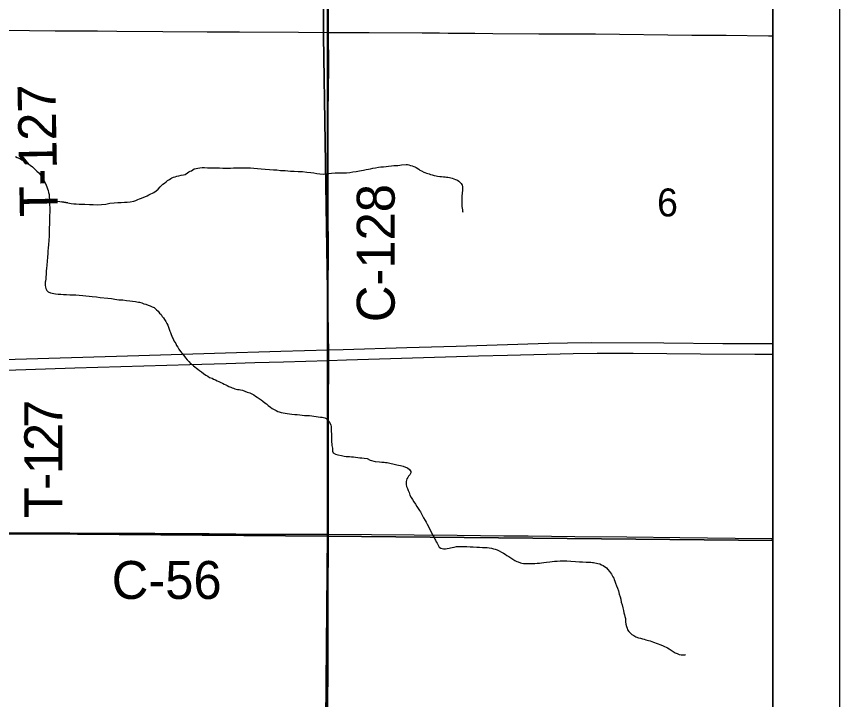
# Model space of a CAD drawing. Extents: x -17 to 88, y -5 to 22.
# Drawn here: x 8.268 to 9.5, y 18.897 to 19.92 of the extents above; entities that cross this region are included whole.
import ezdxf

# ---------------------------------------------------------------- set-up
doc = ezdxf.new("R2010")
doc.units = 0
for name, color, linetype in [('GM_X_County_Road', 7, 'Continuous'), ('GM_X_County_Road_Text', 7, 'Continuous'), ('GM_X_Minor_River', 7, 'Continuous'), ('GM_X_Section', 7, 'Continuous'), ('GM_X_Section_Text', 7, 'Continuous'), ('GM_X_Township', 7, 'Continuous'), ('GM_X_Township_Road', 7, 'Continuous'), ('GM_X_Township_Road_Text', 7, 'Continuous'), ('GM_X_US_Route', 7, 'Continuous'), ('SH_Data', 7, 'Continuous')]:
    doc.layers.add(name, color=color, linetype=linetype)

msp = doc.modelspace()

# ---------------------------------------------------------------- linework, layer by layer
at = {"layer": 'GM_X_County_Road'}
for points in [[(8.7347, 19.8958), (8.7347, 19.9018), (8.7346, 19.9229), (8.7345, 19.9503), (8.7345, 19.9913), (8.7345, 20.0248), (8.7345, 20.0534), (8.7345, 20.0913), (8.7345, 20.1174), (8.7345, 20.1646)], [(8.7345, 19.4204), (8.7345, 19.43), (8.7345, 19.4561), (8.7345, 19.5168), (8.7347, 19.5616), (8.7349, 19.5813), (8.7344, 19.6151), (8.7344, 19.6362), (8.7345, 19.6617), (8.7344, 19.6816), (8.7345, 19.7307), (8.7345, 19.7611), (8.7345, 19.7847), (8.7348, 19.8004), (8.735, 19.8164), (8.7352, 19.8367), (8.7352, 19.8565), (8.7348, 19.8832), (8.7347, 19.8958)], [(8.7345, 19.4044), (8.7345, 19.4133), (8.7345, 19.4204)], [(8.7348, 19.1441), (8.7347, 19.1665), (8.735, 19.1901), (8.7347, 19.2274), (8.7346, 19.2802), (8.7345, 19.3169), (8.7345, 19.3983), (8.7345, 19.4044)], [(8.237, 19.1467), (8.3475, 19.1462), (8.4749, 19.1455), (8.5563, 19.145), (8.5961, 19.1448), (8.6526, 19.1443), (8.7005, 19.1443), (8.7348, 19.1441)], [(8.733, 18.1413), (8.7329, 18.1995), (8.7329, 18.2468), (8.733, 18.2834), (8.7331, 18.3338), (8.7331, 18.3692), (8.7333, 18.4114), (8.7335, 18.4661), (8.7337, 18.5134), (8.7337, 18.583), (8.7338, 18.6588), (8.734, 18.765), (8.734, 18.8744), (8.7343, 18.9558), (8.7343, 19.0435), (8.7348, 19.1441)], [(8.7348, 19.1441), (8.9273, 19.1427), (8.9975, 19.1419), (9.0336, 19.1416), (9.1038, 19.1407), (9.1814, 19.1401), (9.261, 19.1394), (9.3436, 19.1383), (9.3977, 19.1378), (9.4, 19.1378)]]:
    msp.add_lwpolyline(points, dxfattribs=at)
at = {"layer": 'GM_X_Minor_River'}
for points in [[(8.266, 19.7098), (8.2687, 19.7083), (8.2728, 19.7067), (8.2754, 19.7051), (8.2784, 19.7032), (8.2815, 19.7012), (8.2848, 19.6992), (8.2882, 19.6969), (8.2916, 19.6942), (8.295, 19.6911), (8.2979, 19.688), (8.3009, 19.6856), (8.3032, 19.6829), (8.305, 19.6795), (8.3072, 19.6768), (8.3083, 19.6745), (8.312, 19.6668), (8.3131, 19.6642), (8.3142, 19.6615), (8.3149, 19.6588), (8.3156, 19.6558), (8.3163, 19.6527), (8.3166, 19.65), (8.3169, 19.6451), (8.3172, 19.6413), (8.3171, 19.6375), (8.3174, 19.6333), (8.3174, 19.6291), (8.3173, 19.6257), (8.3172, 19.6227), (8.3172, 19.6181), (8.3171, 19.6132), (8.317, 19.6083), (8.3165, 19.603), (8.3164, 19.5969), (8.3163, 19.5912), (8.3158, 19.584), (8.3153, 19.5779), (8.3148, 19.5726), (8.3143, 19.5688), (8.3143, 19.5646), (8.3141, 19.5589), (8.3137, 19.5529), (8.3132, 19.5472), (8.3127, 19.5423), (8.3122, 19.5385), (8.3118, 19.5347), (8.3118, 19.5328), (8.3113, 19.5301), (8.3113, 19.5267), (8.3108, 19.5233), (8.3104, 19.5214), (8.3107, 19.5172), (8.311, 19.5142), (8.3114, 19.5123), (8.3128, 19.5092), (8.3151, 19.5073), (8.3185, 19.5057), (8.326, 19.504), (8.3302, 19.5036), (8.334, 19.5035), (8.3378, 19.5034), (8.3424, 19.503), (8.3473, 19.5029), (8.3519, 19.5028), (8.3564, 19.5027), (8.3614, 19.5023), (8.3667, 19.5018), (8.3716, 19.5013), (8.3766, 19.5008), (8.3811, 19.5004), (8.3876, 19.4995), (8.3929, 19.4986), (8.4042, 19.4977), (8.4096, 19.4972), (8.4149, 19.4963), (8.4209, 19.4954), (8.4266, 19.495), (8.4323, 19.4941), (8.4373, 19.4936), (8.4414, 19.4932), (8.4456, 19.4927), (8.4479, 19.4923), (8.4501, 19.4919), (8.452, 19.4915), (8.4554, 19.4906), (8.4585, 19.4894), (8.4611, 19.4886), (8.4645, 19.4874), (8.4679, 19.4862), (8.4709, 19.4846), (8.4736, 19.4835), (8.4754, 19.4823), (8.4773, 19.4804), (8.4795, 19.478), (8.4818, 19.4753), (8.484, 19.473), (8.4859, 19.4703), (8.4877, 19.468), (8.4892, 19.4657), (8.4914, 19.4626)], [(8.7564, 19.6852), (8.7617, 19.6854), (8.7667, 19.6861), (8.7713, 19.6868), (8.7762, 19.6874), (8.7812, 19.6885), (8.7873, 19.6895), (8.7911, 19.6902), (8.7945, 19.6909), (8.7976, 19.6916), (8.8014, 19.6923), (8.8052, 19.693), (8.8094, 19.6937), (8.8132, 19.6944), (8.817, 19.6943), (8.8212, 19.695), (8.8247, 19.6953), (8.8292, 19.696), (8.8327, 19.6963), (8.8357, 19.6966), (8.8384, 19.6965), (8.8414, 19.6969), (8.8441, 19.6972), (8.8513, 19.6978), (8.8532, 19.6978), (8.8551, 19.6974), (8.8574, 19.6966), (8.86, 19.6961), (8.8623, 19.695), (8.8642, 19.6942), (8.8661, 19.6934), (8.8698, 19.691), (8.8717, 19.6895), (8.8739, 19.6883), (8.8773, 19.6863), (8.8792, 19.6859), (8.8815, 19.6851), (8.8853, 19.6839), (8.8875, 19.6831), (8.8902, 19.6823), (8.8932, 19.6815), (8.8959, 19.681), (8.8981, 19.6806), (8.9015, 19.6798), (8.9038, 19.6798), (8.9069, 19.6793), (8.9095, 19.6793), (8.9114, 19.6789), (8.9137, 19.6788), (8.916, 19.6784), (8.9179, 19.678), (8.9198, 19.6776), (8.9224, 19.6764), (8.925, 19.6756), (8.9277, 19.6744), (8.9299, 19.6728), (8.9333, 19.6693), (8.9348, 19.667), (8.9355, 19.6647), (8.9354, 19.6628), (8.9354, 19.6594), (8.9345, 19.6503), (8.9344, 19.6469), (8.9343, 19.6431), (8.9343, 19.6401), (8.9346, 19.6378), (8.9345, 19.6351), (8.9349, 19.6325), (8.9352, 19.6298), (8.9355, 19.6275), (8.9363, 19.6264), (8.9359, 19.6264)], [(8.3169, 19.6451), (8.3446, 19.6404), (8.3355, 19.6421), (8.3446, 19.6404), (8.3495, 19.6396), (8.3533, 19.6391), (8.3571, 19.639), (8.3613, 19.6386), (8.3654, 19.6385), (8.37, 19.6384), (8.3768, 19.6379), (8.3825, 19.6378), (8.3886, 19.6377), (8.3951, 19.638), (8.4012, 19.6386), (8.4073, 19.64), (8.4138, 19.6406), (8.4195, 19.6409), (8.4244, 19.6412), (8.4294, 19.6415), (8.4332, 19.6414), (8.4378, 19.6421), (8.4431, 19.6431), (8.4462, 19.6442), (8.4492, 19.6453), (8.4519, 19.6464), (8.4546, 19.6475), (8.4634, 19.6511), (8.4657, 19.6522), (8.4688, 19.6537), (8.4711, 19.6548), (8.4734, 19.6559), (8.4765, 19.6585), (8.4795, 19.6611), (8.4827, 19.6644), (8.485, 19.6667), (8.4869, 19.6685), (8.4892, 19.67), (8.4915, 19.6719), (8.4939, 19.6741), (8.4965, 19.6756), (8.4985, 19.6767), (8.5004, 19.6778), (8.5027, 19.6789), (8.505, 19.6796), (8.5077, 19.6803), (8.5107, 19.681), (8.5142, 19.6821), (8.5176, 19.6824), (8.5199, 19.6831), (8.5237, 19.6853), (8.5257, 19.6868), (8.5276, 19.6879), (8.5295, 19.6886), (8.5314, 19.6897), (8.5337, 19.6912), (8.5364, 19.6919), (8.5391, 19.6926), (8.5421, 19.6929), (8.5455, 19.6933), (8.5493, 19.6932), (8.5535, 19.6931), (8.5588, 19.693), (8.5634, 19.6929), (8.5672, 19.6929), (8.5718, 19.6928), (8.5763, 19.6923), (8.5805, 19.6922), (8.5843, 19.6925), (8.5881, 19.6925), (8.5923, 19.6928), (8.5965, 19.6927), (8.6007, 19.693), (8.6136, 19.6931), (8.6178, 19.6927), (8.6231, 19.6922), (8.6284, 19.6917), (8.6337, 19.6912), (8.6398, 19.6907), (8.6462, 19.6902), (8.6523, 19.6901), (8.6576, 19.6897), (8.6629, 19.6888), (8.6698, 19.6887), (8.674, 19.6882), (8.6781, 19.6878), (8.6835, 19.6877), (8.6892, 19.6875), (8.6956, 19.6874), (8.7024, 19.6862), (8.7081, 19.6857), (8.7127, 19.6852), (8.7172, 19.6844), (8.7218, 19.6839), (8.7275, 19.6834), (8.7309, 19.6841), (8.7351, 19.6844), (8.7393, 19.6851), (8.7446, 19.6854), (8.7503, 19.6853), (8.7564, 19.6852)], [(8.4914, 19.4626), (8.4929, 19.4599), (8.494, 19.4573), (8.4972, 19.4485), (8.4983, 19.4462), (8.499, 19.4435), (8.5001, 19.4408), (8.5012, 19.4385), (8.5023, 19.4366), (8.5034, 19.4339), (8.5045, 19.432), (8.506, 19.4297), (8.5071, 19.427), (8.509, 19.4243), (8.5108, 19.4213), (8.5134, 19.4178), (8.5156, 19.4147), (8.5182, 19.4116), (8.5204, 19.4085), (8.523, 19.4055), (8.5257, 19.4027), (8.5283, 19.4), (8.5305, 19.3985), (8.5324, 19.3965), (8.5346, 19.3946), (8.5369, 19.3927), (8.5391, 19.3911), (8.5414, 19.3892), (8.5444, 19.3872), (8.5478, 19.3849), (8.5511, 19.3825), (8.5541, 19.3809), (8.5568, 19.379), (8.5605, 19.3778), (8.5628, 19.3766), (8.5654, 19.3754), (8.5681, 19.3739), (8.5707, 19.3727), (8.5734, 19.3715), (8.576, 19.3703), (8.5786, 19.3691), (8.5809, 19.3679), (8.5832, 19.3667), (8.5854, 19.3656), (8.5884, 19.3644), (8.5907, 19.3636), (8.5926, 19.3628), (8.5945, 19.362), (8.5967, 19.3616), (8.5986, 19.3611), (8.6009, 19.3607), (8.6032, 19.3603), (8.6058, 19.3599), (8.613, 19.3571), (8.6168, 19.3559), (8.6198, 19.3543), (8.6228, 19.3527), (8.6254, 19.3511), (8.6281, 19.3492), (8.6311, 19.3472), (8.6341, 19.3453), (8.6363, 19.3434), (8.6393, 19.341), (8.642, 19.3394), (8.6442, 19.3371), (8.6479, 19.3344), (8.6506, 19.3325), (8.6536, 19.3309), (8.6562, 19.3293), (8.6589, 19.3281), (8.6611, 19.3273), (8.6638, 19.3265), (8.6668, 19.3257), (8.6698, 19.3253), (8.6729, 19.3248), (8.6763, 19.3244), (8.6801, 19.3239), (8.6846, 19.3235), (8.688, 19.3234), (8.6918, 19.323), (8.6952, 19.3225), (8.699, 19.3221), (8.7028, 19.322), (8.7063, 19.3219), (8.7097, 19.3215), (8.7127, 19.321), (8.7161, 19.3206), (8.7195, 19.3202), (8.7229, 19.3197), (8.7252, 19.3193), (8.7275, 19.3189), (8.7294, 19.3185), (8.7313, 19.3173), (8.7342, 19.3138), (8.7365, 19.3115), (8.7383, 19.308), (8.7386, 19.305), (8.739, 19.3019), (8.7389, 19.3001), (8.7389, 19.2974), (8.7392, 19.2951)], [(8.7392, 19.2951), (8.7392, 19.2917), (8.7391, 19.2894), (8.7391, 19.2875), (8.7394, 19.2849), (8.7393, 19.2818), (8.7397, 19.2795), (8.74, 19.2769), (8.7404, 19.275), (8.7407, 19.2731), (8.7407, 19.2712), (8.741, 19.2685), (8.7417, 19.2662), (8.7451, 19.2642), (8.7485, 19.263), (8.7542, 19.2618), (8.7584, 19.261), (8.7614, 19.2605), (8.764, 19.2605), (8.7663, 19.2604), (8.769, 19.26), (8.772, 19.2599), (8.775, 19.2595), (8.7785, 19.2591), (8.7815, 19.2586), (8.7845, 19.2586), (8.7883, 19.2581), (8.7925, 19.2573), (8.797, 19.2553), (8.8046, 19.2533), (8.811, 19.2528), (8.8148, 19.2523), (8.8179, 19.2519), (8.8201, 19.2515), (8.8224, 19.2514), (8.8247, 19.251), (8.8349, 19.2485), (8.8372, 19.2481), (8.8395, 19.2477), (8.8425, 19.2469), (8.8448, 19.2464), (8.8467, 19.246), (8.8501, 19.2448), (8.8531, 19.2436), (8.8561, 19.2409), (8.8583, 19.2382), (8.8583, 19.2359), (8.8567, 19.2333), (8.8547, 19.2311), (8.8536, 19.2292), (8.852, 19.2269), (8.8512, 19.2232), (8.8511, 19.2209), (8.8511, 19.2186), (8.8518, 19.2156), (8.8529, 19.2125), (8.854, 19.2094), (8.8554, 19.2068), (8.8565, 19.2026), (8.8587, 19.1991), (8.8605, 19.196), (8.8624, 19.1926), (8.865, 19.1891), (8.8668, 19.1857), (8.869, 19.1826), (8.8709, 19.1799), (8.8724, 19.1776), (8.8738, 19.1749), (8.8753, 19.1718), (8.8771, 19.1688), (8.8794, 19.1649), (8.8808, 19.1622), (8.8827, 19.1592), (8.8845, 19.1557), (8.8896, 19.145), (8.8915, 19.1419), (8.8929, 19.1392), (8.894, 19.1369), (8.8951, 19.135), (8.8962, 19.1327), (8.8973, 19.1308), (8.8985, 19.1289), (8.8996, 19.1266), (8.9007, 19.1246), (8.9029, 19.1231), (8.9048, 19.1227), (8.9071, 19.1223), (8.9101, 19.1222), (8.9124, 19.1229), (8.9155, 19.1232), (8.9174, 19.1236), (8.92, 19.1243), (8.9231, 19.125), (8.9265, 19.1257), (8.9307, 19.1256), (8.9345, 19.1259), (8.9383, 19.1258), (8.9421, 19.1258), (8.9467, 19.1253), (8.9512, 19.1252), (8.9569, 19.1247)], [(8.9569, 19.1247), (8.9611, 19.1247), (8.9653, 19.1242), (8.9691, 19.1241), (8.9725, 19.1241), (8.9755, 19.1236), (8.979, 19.1232), (8.9816, 19.1224), (8.9842, 19.1216), (8.9873, 19.1208), (8.9967, 19.116), (8.9993, 19.1145), (9.0019, 19.1125), (9.0049, 19.1106), (9.0076, 19.1086), (9.011, 19.1066), (9.014, 19.1047), (9.0166, 19.1035), (9.0189, 19.1027), (9.0223, 19.1015), (9.0242, 19.1007), (9.0268, 19.1003), (9.0291, 19.1002), (9.0317, 19.1002), (9.0356, 19.1001), (9.0394, 19.1004), (9.0435, 19.1003), (9.0473, 19.1007), (9.0508, 19.1006), (9.0538, 19.1013), (9.0573, 19.1016), (9.0611, 19.1023), (9.066, 19.1026), (9.0698, 19.1033), (9.0733, 19.1036), (9.0771, 19.1039), (9.0816, 19.1042), (9.0866, 19.1045), (9.0915, 19.1044), (9.0976, 19.1039), (9.1044, 19.1034), (9.1105, 19.1029), (9.1151, 19.1028), (9.1204, 19.1023), (9.1242, 19.1023), (9.1276, 19.1022), (9.1299, 19.1018), (9.1318, 19.1017), (9.1337, 19.1013), (9.1359, 19.1009), (9.1382, 19.1005), (9.1412, 19.0997), (9.1435, 19.0985), (9.1461, 19.0973), (9.151, 19.0938), (9.1529, 19.0915), (9.1555, 19.0884), (9.157, 19.0861), (9.1584, 19.0842), (9.1595, 19.0822), (9.1606, 19.0803), (9.1618, 19.0784), (9.1625, 19.0761), (9.1636, 19.0738), (9.1647, 19.0708), (9.1661, 19.0669), (9.1675, 19.0631), (9.169, 19.0593), (9.17, 19.0543), (9.1715, 19.0505), (9.1726, 19.0467), (9.1732, 19.0425), (9.1743, 19.0383), (9.1754, 19.0341), (9.1764, 19.0299), (9.1771, 19.0265), (9.1782, 19.0234), (9.1785, 19.0208), (9.1793, 19.0181), (9.1796, 19.0162), (9.1795, 19.0131), (9.1798, 19.0093), (9.1809, 19.0059), (9.182, 19.0032), (9.1827, 19.0009), (9.1846, 18.9982), (9.1868, 18.9959), (9.1891, 18.994), (9.1921, 18.9924), (9.1951, 18.9904), (9.1989, 18.9892), (9.2019, 18.9884), (9.2049, 18.9876), (9.2076, 18.9868), (9.2098, 18.986), (9.2121, 18.9856), (9.214, 18.9852), (9.2163, 18.9844), (9.2189, 18.9835), (9.2215, 18.9824), (9.2325, 18.9784)], [(9.2325, 18.9784), (9.2359, 18.9768), (9.2423, 18.974), (9.2449, 18.9724), (9.2494, 18.9697), (9.2539, 18.9666), (9.257, 18.9654), (9.26, 18.9642), (9.263, 18.9637), (9.2653, 18.9633), (9.268, 18.9633), (9.2687, 18.9633), (9.2695, 18.9632)]]:
    msp.add_lwpolyline(points, dxfattribs=at)
at = {"layer": 'GM_X_Section'}
for p, q in [((9.4, 19.1346), (9.4, 20.1711)), ((9.4, 18.1346), (9.4, 19.1346))]:
    msp.add_line(p, q, dxfattribs=at)
for points in [[(7.7295, 20.169), (8.7328, 20.1648), (8.7326, 19.1414), (7.7351, 19.1493)], [(8.7326, 19.1414), (8.7311, 18.1404), (7.729, 18.1476), (7.7351, 19.1493)]]:
    msp.add_lwpolyline(points, close=True, dxfattribs=at)
for points in [[(9.4, 20.1711), (8.7328, 20.1648), (8.7326, 19.1414), (9.4, 19.1346)], [(9.4, 19.1346), (8.7326, 19.1414), (8.7311, 18.1404), (9.4, 18.1346)]]:
    msp.add_lwpolyline(points, dxfattribs=at)
at = {"layer": 'GM_X_Township'}
for points in [[(5.0464, 18.1513), (5.7149, 18.1469), (5.7215, 18.6472), (5.7225, 19.1491), (6.2534, 19.1527), (6.9691, 19.1558), (7.2261, 19.1535), (7.7361, 19.149), (8.236, 19.1446), (8.7331, 19.1436), (8.7348, 19.4138), (8.7274, 19.89), (8.7281, 20.1646), (7.7177, 20.1665), (7.7206, 20.6696), (7.7218, 20.9)], [(8.709, 14.1), (9.4, 14.1), (9.4, 20.1669)], [(9.4, 20.1669), (8.7281, 20.1646), (8.7274, 19.89), (8.7348, 19.4138), (8.7331, 19.1436), (8.7241, 18.1383), (8.7317, 17.1395), (8.7273, 16.2993), (8.7261, 16.1499), (8.7243, 15.8906), (8.7164, 14.7728), (8.709, 14.1)], [(8.709, 14.1), (8.7164, 14.7728), (8.7243, 15.8906), (8.7261, 16.1499), (8.7273, 16.2993), (8.7317, 17.1395), (8.7241, 18.1383), (8.7331, 19.1436), (8.236, 19.1446), (7.7361, 19.149), (7.2261, 19.1535), (6.9691, 19.1558), (6.2534, 19.1527), (5.7225, 19.1491), (5.7215, 18.6472), (5.7149, 18.1469), (5.0464, 18.1513)]]:
    msp.add_lwpolyline(points, dxfattribs=at)
at = {"layer": 'GM_X_Township_Road'}
for points in [[(8.2368, 19.8993), (8.2872, 19.8988), (8.3257, 19.8981), (8.3437, 19.898), (8.3493, 19.8981), (8.3891, 19.8979), (8.4177, 19.8976), (8.4866, 19.8971), (8.5531, 19.8966), (8.6016, 19.8964), (8.6898, 19.896), (8.7347, 19.8958)], [(8.7347, 19.8958), (8.7955, 19.8955), (8.875, 19.895), (8.9008, 19.8949), (8.914, 19.8948), (8.9216, 19.8948), (8.954, 19.8946), (8.9807, 19.8943), (9.0496, 19.8938), (9.0701, 19.8938), (9.1347, 19.8934), (9.2789, 19.8917), (9.3304, 19.8915), (9.3938, 19.8907), (9.4, 19.8906)]]:
    msp.add_lwpolyline(points, dxfattribs=at)
at = {"layer": 'GM_X_US_Route'}
for points in [[(8.2317, 19.4052), (8.451, 19.4118), (8.564, 19.4152), (8.6634, 19.4183), (8.7345, 19.4204), (8.7566, 19.4209), (8.8523, 19.4238), (8.9259, 19.426), (9.0641, 19.4302), (9.0927, 19.4309), (9.1281, 19.4313), (9.2369, 19.4308), (9.3251, 19.43), (9.3836, 19.4298), (9.4, 19.4297)], [(8.222, 19.389), (8.3548, 19.3931), (8.5269, 19.3982), (8.5815, 19.3996), (8.6244, 19.4011), (8.6673, 19.4025), (8.7345, 19.4044), (8.7617, 19.4052), (8.9592, 19.4111), (9.0027, 19.4124), (9.1009, 19.415), (9.137, 19.4154), (9.1736, 19.4154), (9.1908, 19.4153), (9.2917, 19.4145), (9.3734, 19.4139), (9.4, 19.4138)]]:
    msp.add_lwpolyline(points, dxfattribs=at)
at = {"layer": 'SH_Data'}
for p, q in [((9.5, 21), (9.5, 14)), ((9.4, 20.9), (9.4, 14.1))]:
    msp.add_line(p, q, dxfattribs=at)

# ---------------------------------------------------------------- texts
at = {"layer": 'GM_X_County_Road_Text'}
for s, rotation, p in [('C-128', 90, (8.8339, 19.4617)), ('C-56', 0, (8.4101, 19.0472))]:
    msp.add_text(s, height=0.05682, rotation=rotation, dxfattribs=at).set_placement(p)
at = {"layer": 'GM_X_Section_Text'}
msp.add_text('6', height=0.0419, rotation=0, dxfattribs=at).set_placement((9.2268, 19.6201))
at = {"layer": 'GM_X_Township_Road_Text'}
for s, height, rotation, p in [('T-127', 0.05682, 91.0755, (8.3295, 19.6201)), ('7', 0.0568, 90.1324, (8.3361, 19.3034)), ('2', 0.0568, 90.0792, (8.3361, 19.2686)), ('1', 0.0568, 90.075, (8.3362, 19.2339)), ('-', 0.0568, 90.073, (8.3362, 19.2107)), ('T', 0.0568, 90.0726, (8.3362, 19.1683))]:
    msp.add_text(s, height=height, rotation=rotation, dxfattribs=at).set_placement(p)

doc.saveas('drawing.dxf')
